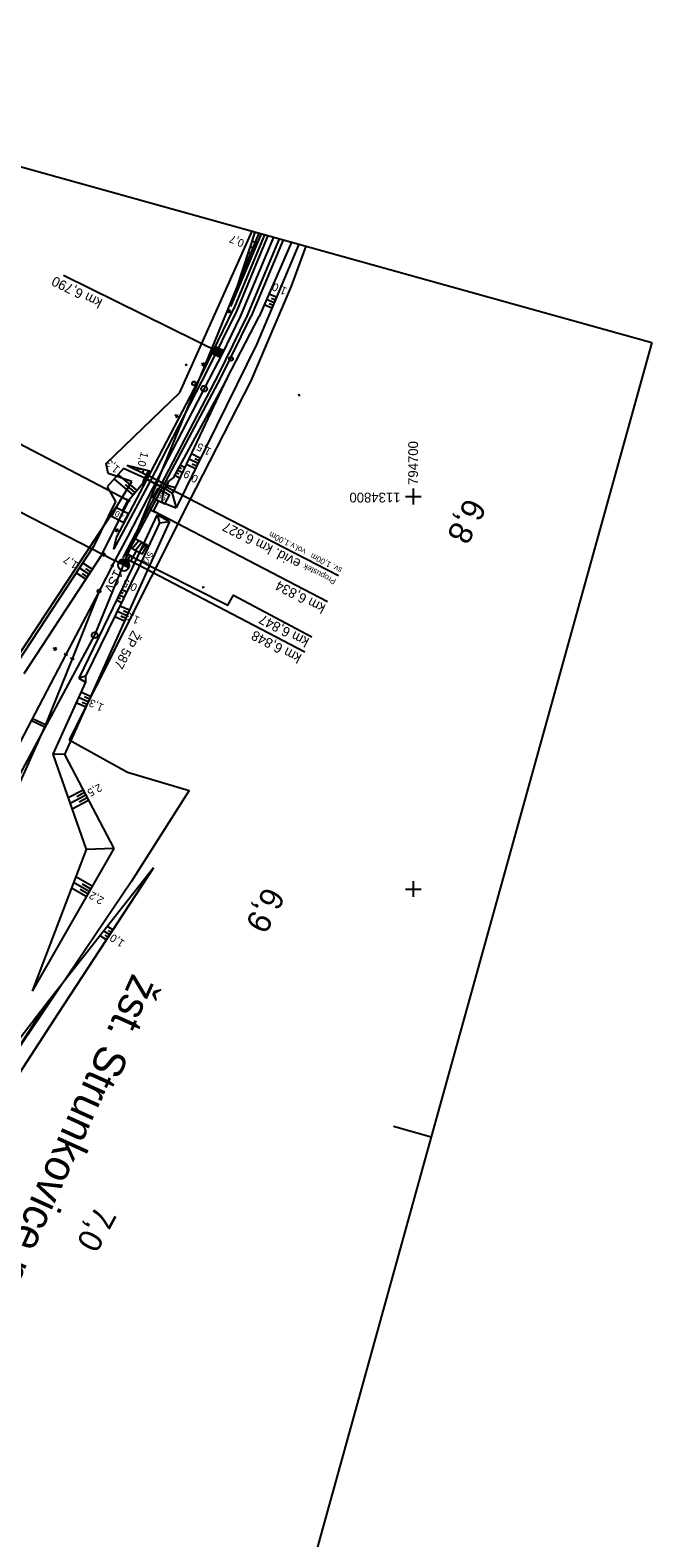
# Model space of a CAD drawing. Extents: x -795094 to -794639, y -1135368 to -1134681.
# Drawn here: x -794797.7 to -794639.2, y -1135065.2 to -1134681.2 of the extents above; entities that cross this region are included whole.
import ezdxf

# ---------------------------------------------------------------- set-up
doc = ezdxf.new("R2010")
doc.units = 0
for name, color, linetype in [('0381KM005-009P - Vrstva 1', 7, 'Continuous'), ('0381KM005-009P - Vrstva 19', 7, 'Continuous'), ('0381KM005-009P - Vrstva 2', 7, 'Continuous'), ('0381KM005-009P - Vrstva 23', 7, 'Continuous'), ('0381KM005-009P - Vrstva 28', 7, 'Continuous'), ('0381KM005-009P - Vrstva 3', 7, 'Continuous'), ('0381KM005-009P - Vrstva 33', 7, 'Continuous'), ('0381KM005-009P - Vrstva 4', 7, 'Continuous'), ('0381KM005-009P - Vrstva 48', 7, 'Continuous'), ('0381KM005-009P - Vrstva 49', 7, 'Continuous'), ('0381KM005-009P - Vrstva 5', 7, 'Continuous'), ('0381KM005-009P - Vrstva 51', 7, 'Continuous'), ('0381KM005-009P - Vrstva 6', 7, 'Continuous'), ('0381KM005-009P - Vrstva 7', 7, 'Continuous'), ('formát', 7, 'Continuous'), ('hran DP - hran DP', 7, 'Continuous'), ('krizky_1000 - souradnice', 7, 'Continuous'), ('krizky_1000 - Vrstva 1', 7, 'Continuous'), ('vyt_sit - polygon', 7, 'Continuous'), ('vyt_sit - stávající', 7, 'Continuous')]:
    doc.layers.add(name, color=color, linetype=linetype)

msp = doc.modelspace()

# ---------------------------------------------------------------- linework, layer by layer
at = {"layer": '0381KM005-009P - Vrstva 1'}
for points in [[(-794735.66, -1134733.94), (-794744.1, -1134754.13), (-794748.76, -1134763.69), (-794750.73, -1134767.6), (-794757.62, -1134780.92)], [(-794757.62, -1134780.92), (-794772.8, -1134810.07), (-794776.07, -1134816.32)], [(-794776.07, -1134816.32), (-794776.43, -1134817.02), (-794780.11, -1134824.07), (-794788.58, -1134840.28)], [(-794776.07, -1134816.32), (-794776.43, -1134817.02), (-794780.11, -1134824.07), (-794786.96, -1134841.36)], [(-794788.58, -1134840.28), (-794803.19, -1134868.16), (-794810.38, -1134881.86), (-794818.66, -1134897.6), (-794826.62, -1134912.5), (-794834.33, -1134926.85), (-794861.92, -1134977.99)], [(-794786.96, -1134841.36), (-794793.84, -1134858.32), (-794800.91, -1134874.12), (-794807.73, -1134887.87), (-794826.52, -1134924.29), (-794833.34, -1134937.13), (-794839.37, -1134947.86), (-794840.75, -1134950.16), (-794846.08, -1134958.61), (-794850.88, -1134965.55), (-794860.1, -1134978.74)]]:
    msp.add_lwpolyline(points, dxfattribs=at)
at = {"layer": '0381KM005-009P - Vrstva 19'}
for p, q in [((-794767.26, -1134793.5), (-794768.87, -1134796.52)), ((-794768.87, -1134796.52), (-794768.27, -1134795.41)), ((-794768.27, -1134795.41), (-794767.82, -1134794.57)), ((-794768.27, -1134795.41), (-794768.27, -1134795.41)), ((-794763.3, -1134797.99), (-794768.27, -1134795.41)), ((-794768.27, -1134795.41), (-794763.33, -1134798.06)), ((-794767.82, -1134794.57), (-794767.26, -1134793.5)), ((-794767.82, -1134794.57), (-794767.82, -1134794.57)), ((-794762.85, -1134797.19), (-794767.82, -1134794.57)), ((-794762.89, -1134797.15), (-794767.82, -1134794.57)), ((-794763.85, -1134798.98), (-794762.37, -1134796.11)), ((-794762.89, -1134797.15), (-794763.33, -1134798.06)), ((-794762.85, -1134797.19), (-794762.89, -1134797.15)), ((-794762.37, -1134796.11), (-794762.85, -1134797.19)), ((-794763.3, -1134797.99), (-794763.85, -1134798.98)), ((-794763.33, -1134798.06), (-794763.3, -1134797.99)), ((-794719.1, -1134820.2), (-794763.06, -1134797.51))]:
    msp.add_line(p, q, dxfattribs=at)
at = {"layer": '0381KM005-009P - Vrstva 2'}
for p, q in [((-794815.95, -1134795.81), (-794776.07, -1134816.32)), ((-794775.14, -1134816.79), (-794776.07, -1134816.32)), ((-794774.93, -1134816.49), (-794774.77, -1134816.98)), ((-794774.61, -1134816.22), (-794774.29, -1134817.23)), ((-794774.26, -1134816.06), (-794773.81, -1134817.48)), ((-794773.89, -1134816), (-794773.33, -1134817.72)), ((-794773.47, -1134816.05), (-794772.86, -1134817.97)), ((-794773, -1134816.26), (-794772.46, -1134817.95)), ((-794772.54, -1134818.13), (-794775.14, -1134816.79)), ((-794772.54, -1134818.13), (-794772.54, -1134818.13)), ((-794780.11, -1134824.07), (-794786.96, -1134841.36)), ((-794788.14, -1134840.51), (-794789.03, -1134840.05)), ((-794786.49, -1134841.55), (-794787.42, -1134841.18))]:
    msp.add_line(p, q, dxfattribs=at)
for points in [[(-794776.07, -1134816.32), (-794776.43, -1134817.02), (-794780.11, -1134824.07), (-794788.58, -1134840.28)], [(-794776.64, -1134817.99), (-794776.43, -1134817.02), (-794777.1, -1134817.76)]]:
    msp.add_lwpolyline(points, dxfattribs=at)
msp.add_circle((-794780.11, -1134824.07), 0.4, dxfattribs=at)
for start, end in [(332.7997, 152.7606), (152.7102, 333.1797)]:
    msp.add_arc((-794773.84, -1134817.46), 1.46, start, end, dxfattribs=at)
at = {"layer": '0381KM005-009P - Vrstva 28'}
msp.add_line((-794746.44, -1134764.88), (-794746.48, -1134764.97), dxfattribs=at)
msp.add_circle((-794746.46, -1134764.93), 0.5, dxfattribs=at)
at = {"layer": '0381KM005-009P - Vrstva 3'}
for p, q in [((-794748.76, -1134763.69), (-794789.21, -1134743.71)), ((-794750.35, -1134762.39), (-794749.67, -1134764.36)), ((-794750.12, -1134761.92), (-794749.2, -1134764.59)), ((-794749.64, -1134762.15), (-794748.96, -1134764.11)), ((-794749.16, -1134762.38), (-794748.73, -1134763.64)), ((-794748.69, -1134762.61), (-794748.5, -1134763.16)), ((-794750.81, -1134763.35), (-794750.63, -1134763.89)), ((-794750.58, -1134762.87), (-794750.15, -1134764.12))]:
    msp.add_line(p, q, dxfattribs=at)
msp.add_lwpolyline([(-794748.32, -1134762.79), (-794749.2, -1134764.59), (-794750.99, -1134763.71), (-794750.12, -1134761.92)], close=True, dxfattribs=at)
at = {"layer": '0381KM005-009P - Vrstva 33'}
msp.add_line((-794768.83, -1134796.2), (-794767.55, -1134793.7), dxfattribs=at)
at = {"layer": '0381KM005-009P - Vrstva 4'}
for points in [[(-794737.95, -1134733.31), (-794745.79, -1134752.29)], [(-794737.06, -1134733.55), (-794744.97, -1134752.65)], [(-794734.21, -1134734.35), (-794742.45, -1134754.09)], [(-794733.14, -1134734.64), (-794741.33, -1134754.03)], [(-794744.97, -1134752.65), (-794752.57, -1134767.89), (-794767.17, -1134796.25), (-794776.32, -1134813.35), (-794775.69, -1134810.46), (-794767.89, -1134795.76), (-794753.75, -1134768.59), (-794745.79, -1134752.29)], [(-794742.45, -1134754.09), (-794749.67, -1134768.83), (-794764.43, -1134797.23), (-794773.98, -1134815.47), (-794772.27, -1134813.39), (-794763.8, -1134797.42), (-794749.03, -1134769.75), (-794741.33, -1134754.03)]]:
    msp.add_lwpolyline(points, dxfattribs=at)
at = {"layer": '0381KM005-009P - Vrstva 48'}
for p, q in [((-794739.8, -1134735.54), (-794741.14, -1134734.97)), ((-794740.97, -1134738.3), (-794742.08, -1134737.83)), ((-794740.39, -1134736.92), (-794741.61, -1134736.4)), ((-794740.68, -1134737.61), (-794741.26, -1134737.36)), ((-794740.09, -1134736.23), (-794740.73, -1134735.96)), ((-794736.03, -1134752.03), (-794738.01, -1134751.2)), ((-794735.45, -1134750.65), (-794737.41, -1134749.82)), ((-794734.87, -1134749.26), (-794736.81, -1134748.45)), ((-794735.74, -1134751.34), (-794736.72, -1134750.92)), ((-794735.16, -1134749.96), (-794736.13, -1134749.54)), ((-794754.22, -1134790.28), (-794756.53, -1134789.14)), ((-794770.26, -1134792.73), (-794770.4, -1134793.3)), ((-794769.53, -1134792.91), (-794769.62, -1134793.27)), ((-794768.8, -1134793.1), (-794769.03, -1134793.97)), ((-794760.11, -1134793.21), (-794758.79, -1134793.93)), ((-794759.75, -1134792.55), (-794759.11, -1134792.9)), ((-794759.39, -1134791.89), (-794758.15, -1134792.57)), ((-794755.55, -1134792.97), (-794757.81, -1134791.86)), ((-794754.88, -1134791.63), (-794757.17, -1134790.5)), ((-794755.21, -1134792.3), (-794756.35, -1134791.74)), ((-794754.55, -1134790.95), (-794755.7, -1134790.39)), ((-794771.4, -1134799.56), (-794776.25, -1134795.52)), ((-794770.44, -1134798.41), (-794775.25, -1134794.4)), ((-794770.92, -1134798.98), (-794773.33, -1134796.97)), ((-794760.82, -1134794.53), (-794759.43, -1134795.29)), ((-794760.46, -1134793.87), (-794759.79, -1134794.24)), ((-794783.51, -1134821.05), (-794785.98, -1134819.43)), ((-794782.69, -1134819.79), (-794785.16, -1134818.18)), ((-794783.1, -1134820.42), (-794784.34, -1134819.61)), ((-794781.87, -1134818.54), (-794784.33, -1134816.93)), ((-794782.28, -1134819.17), (-794783.51, -1134818.36)), ((-794774.33, -1134823.66), (-794773.01, -1134824.29)), ((-794775.63, -1134826.36), (-794774.33, -1134826.99)), ((-794775.3, -1134825.69), (-794774.65, -1134826)), ((-794774.98, -1134825.01), (-794773.67, -1134825.64)), ((-794772.39, -1134828.99), (-794774.79, -1134827.92)), ((-794774.65, -1134824.34), (-794774, -1134824.65)), ((-794773.62, -1134831.73), (-794776.11, -1134830.61)), ((-794773.01, -1134830.36), (-794775.45, -1134829.27)), ((-794773.32, -1134831.05), (-794774.55, -1134830.49)), ((-794772.7, -1134829.68), (-794773.91, -1134829.14)), ((-794782.26, -1134850.93), (-794784.73, -1134849.82)), ((-794782.56, -1134851.61), (-794783.8, -1134851.06)), ((-794783.49, -1134853.67), (-794785.97, -1134852.55)), ((-794782.87, -1134852.3), (-794785.35, -1134851.19)), ((-794783.18, -1134852.98), (-794784.42, -1134852.43)), ((-794784.18, -1134874.77), (-794788, -1134876.78)), ((-794783.48, -1134876.09), (-794787.5, -1134878.21)), ((-794782.78, -1134877.42), (-794787, -1134879.64)), ((-794783.83, -1134875.43), (-794785.79, -1134876.46)), ((-794783.13, -1134876.76), (-794785.19, -1134877.84)), ((-794781.89, -1134899.28), (-794786.07, -1134896.89)), ((-794783.38, -1134901.88), (-794787.15, -1134899.73)), ((-794782.63, -1134900.58), (-794786.61, -1134898.31)), ((-794783, -1134901.23), (-794784.94, -1134900.12)), ((-794782.26, -1134899.93), (-794784.3, -1134898.76)), ((-794778.21, -1134912.91), (-794779.82, -1134911.86)), ((-794777.39, -1134911.65), (-794778.88, -1134910.67)), ((-794777.8, -1134912.28), (-794778.58, -1134911.77)), ((-794776.57, -1134910.4), (-794777.95, -1134909.49)), ((-794776.98, -1134911.03), (-794777.7, -1134910.55))]:
    msp.add_line(p, q, dxfattribs=at)
at = {"layer": '0381KM005-009P - Vrstva 49'}
for p, q in [((-794740.37, -1134732.63), (-794746.6, -1134751.57)), ((-794738.76, -1134733.08), (-794746.6, -1134751.57)), ((-794729.18, -1134735.74), (-794739.85, -1134761.11)), ((-794731.07, -1134735.22), (-794739.3, -1134754.18)), ((-794747.45, -1134769.82), (-794739.3, -1134754.18)), ((-794739.85, -1134761.11), (-794760.44, -1134802.9)), ((-794757.66, -1134766.37), (-794758.14, -1134766.52)), ((-794757.97, -1134766.21), (-794757.82, -1134766.69)), ((-794747.45, -1134769.82), (-794761.22, -1134795.28)), ((-794760.61, -1134797.81), (-794747.45, -1134769.82)), ((-794728.89, -1134774.12), (-794729.36, -1134774.28)), ((-794729.21, -1134773.96), (-794729.05, -1134774.44)), ((-794773.87, -1134792.87), (-794778.08, -1134797.54)), ((-794768.27, -1134795.41), (-794773.87, -1134792.87)), ((-794773.02, -1134792.01), (-794767.82, -1134794.57)), ((-794773.02, -1134792.01), (-794767.26, -1134793.5)), ((-794772.33, -1134800.68), (-794768.87, -1134796.52)), ((-794768.27, -1134795.41), (-794768.87, -1134796.52)), ((-794767.82, -1134794.57), (-794767.26, -1134793.5)), ((-794762.37, -1134796.11), (-794763.85, -1134798.98)), ((-794762.85, -1134797.19), (-794762.37, -1134796.11)), ((-794760.61, -1134797.81), (-794762.85, -1134797.19)), ((-794761.22, -1134795.28), (-794762.37, -1134796.11)), ((-794779.34, -1134814.68), (-794772.33, -1134800.68)), ((-794778.08, -1134797.54), (-794775.92, -1134801.3)), ((-794763.85, -1134798.98), (-794764.14, -1134801.43)), ((-794763.3, -1134797.99), (-794763.85, -1134798.98)), ((-794763.3, -1134797.99), (-794761.44, -1134799.24)), ((-794761.44, -1134799.24), (-794760.61, -1134797.81)), ((-794761.44, -1134799.24), (-794760.44, -1134802.9)), ((-794775.92, -1134801.3), (-794781.56, -1134812.71)), ((-794765.33, -1134804.62), (-794771.57, -1134817.97)), ((-794765.33, -1134804.62), (-794764.66, -1134806.73)), ((-794765.33, -1134804.62), (-794762.15, -1134806.37)), ((-794764.14, -1134801.43), (-794760.44, -1134802.9)), ((-794764.66, -1134806.73), (-794770.02, -1134818.19)), ((-794762.15, -1134806.37), (-794768.04, -1134819.3)), ((-794764.66, -1134806.73), (-794762.15, -1134806.37)), ((-794781.56, -1134812.71), (-794806.26, -1134850.22)), ((-794779.34, -1134814.68), (-794799.26, -1134845.15)), ((-794768.04, -1134819.3), (-794788.91, -1134865.74)), ((-794771.57, -1134817.97), (-794785.26, -1134846.3)), ((-794770.02, -1134818.19), (-794783.54, -1134845.78)), ((-794753.32, -1134823.06), (-794753.8, -1134823.21)), ((-794753.64, -1134822.9), (-794753.49, -1134823.38)), ((-794783.54, -1134845.78), (-794785.26, -1134846.3)), ((-794785.26, -1134846.3), (-794783.58, -1134847.29)), ((-794783.54, -1134845.78), (-794783.58, -1134847.29)), ((-794783.58, -1134847.29), (-794791.9, -1134865.62)), ((-794791.9, -1134865.62), (-794783.41, -1134889.91)), ((-794788.91, -1134865.74), (-794791.9, -1134865.62)), ((-794788.91, -1134865.74), (-794776.38, -1134889.62)), ((-794776.38, -1134889.62), (-794797.15, -1134926.02)), ((-794783.41, -1134889.91), (-794797.15, -1134926.02)), ((-794776.38, -1134889.62), (-794783.41, -1134889.91)), ((-794766.19, -1134894.56), (-794792.99, -1134928.57)), ((-794766.19, -1134894.56), (-794790.5, -1134931.65)), ((-794790.5, -1134931.65), (-794824.29, -1134983.58)), ((-794792.99, -1134928.57), (-794819.56, -1134969.3)), ((-794792.99, -1134928.57), (-794819.08, -1134962.42))]:
    msp.add_line(p, q, dxfattribs=at)
at = {"layer": '0381KM005-009P - Vrstva 5'}
for p, q in [((-794808.79, -1134782.22), (-794772.81, -1134800.95)), ((-794772.14, -1134801.3), (-794773.47, -1134800.61)), ((-794766.9, -1134803.37), (-794765.57, -1134804.07)), ((-794721.88, -1134826.8), (-794766.23, -1134803.72))]:
    msp.add_line(p, q, dxfattribs=at)
for points in [[(-794772.81, -1134800.95), (-794774.19, -1134803.61), (-794775.74, -1134802.81), (-794776.9, -1134805.02), (-794773.79, -1134806.64), (-794772.64, -1134804.42), (-794774.19, -1134803.61)], [(-794766.23, -1134803.72), (-794764.85, -1134801.06), (-794763.3, -1134801.87), (-794762.14, -1134799.65), (-794765.25, -1134798.03), (-794766.4, -1134800.25), (-794764.85, -1134801.06)]]:
    msp.add_lwpolyline(points, dxfattribs=at)
at = {"layer": '0381KM005-009P - Vrstva 51'}
msp.add_lwpolyline([(-794871.74, -1135021.34), (-794845.86, -1135006.13), (-794837.37, -1134998.39), (-794824.29, -1134983.58), (-794790.5, -1134931.65), (-794766.19, -1134894.56)], dxfattribs=at)
at = {"layer": '0381KM005-009P - Vrstva 6'}
for p, q in [((-794773.1, -1134816.84), (-794772.18, -1134815.08)), ((-794771.74, -1134815.31), (-794772.62, -1134814.85))]:
    msp.add_line(p, q, dxfattribs=at)
msp.add_lwpolyline([(-794772.18, -1134815.08), (-794747.28, -1134827.67), (-794745.87, -1134825.09), (-794725.88, -1134835.7)], dxfattribs=at)
at = {"layer": '0381KM005-009P - Vrstva 7'}
for p, q in [((-794747.36, -1134752.67), (-794746.44, -1134753.06)), ((-794747.09, -1134753.33), (-794746.71, -1134752.4)), ((-794753.12, -1134766.56), (-794754.01, -1134766.1)), ((-794753.33, -1134765.88), (-794753.79, -1134766.77)), ((-794755.87, -1134771.14), (-794755.92, -1134771.23)), ((-794759.86, -1134779.78), (-794760.75, -1134779.32)), ((-794760.07, -1134779.1), (-794760.53, -1134779.99)), ((-794775.17, -1134808.86), (-794776.06, -1134808.4)), ((-794775.38, -1134808.18), (-794775.84, -1134809.07)), ((-794771.69, -1134813.25), (-794770.09, -1134811.26)), ((-794769.2, -1134811.73), (-794770.8, -1134813.71)), ((-794769.92, -1134814.17), (-794768.32, -1134812.19)), ((-794778.43, -1134815.06), (-794779.32, -1134814.6)), ((-794778.65, -1134814.39), (-794779.11, -1134815.27)), ((-794772.64, -1134816.14), (-794771.31, -1134816.83)), ((-794727.67, -1134839.67), (-794771.97, -1134816.49)), ((-794790.89, -1134839.08), (-794791.78, -1134838.62)), ((-794791.11, -1134838.41), (-794791.57, -1134839.3)), ((-794797.37, -1134857.06), (-794793.96, -1134858.64)), ((-794797.09, -1134856.53), (-794793.74, -1134858.08))]:
    msp.add_line(p, q, dxfattribs=at)
msp.add_lwpolyline([(-794771.97, -1134816.49), (-794770.58, -1134813.83), (-794769.03, -1134814.64), (-794767.87, -1134812.42), (-794770.97, -1134810.8), (-794772.13, -1134813.02), (-794770.58, -1134813.83)], dxfattribs=at)
for centre, radius in [((-794755.9, -1134771.19), 0.5), ((-794753.29, -1134772.54), 0.75)]:
    msp.add_circle(centre, radius, dxfattribs=at)
at = {"layer": 'formát'}
for p, q in [((-794925.31, -1134681.22), (-794639.16, -1134760.77)), ((-794639.16, -1134760.77), (-794695.41, -1134963.1)), ((-794705.05, -1134960.42), (-794695.41, -1134963.1)), ((-794705.05, -1134960.42), (-794695.41, -1134963.1)), ((-794695.41, -1134963.1), (-794751.67, -1135165.42))]:
    msp.add_line(p, q, dxfattribs=at)
at = {"layer": 'hran DP - hran DP'}
for p, q in [((-794759.53, -1134773.54), (-794741.05, -1134732.44)), ((-794727.43, -1134736.23), (-794731.15, -1134746.39)), ((-794731.15, -1134746.39), (-794741.45, -1134770.5)), ((-794778.33, -1134791.56), (-794759.53, -1134773.54)), ((-794741.45, -1134770.5), (-794758.9, -1134804.63)), ((-794777.82, -1134794.18), (-794778.33, -1134791.56)), ((-794771.78, -1134796.16), (-794777.82, -1134794.18)), ((-794775.44, -1134802.2), (-794771.78, -1134796.16)), ((-794808.02, -1134851.51), (-794775.44, -1134802.2)), ((-794758.9, -1134804.63), (-794759.9, -1134806.76)), ((-794759.9, -1134806.76), (-794787.72, -1134861.99)), ((-794787.72, -1134861.99), (-794772.84, -1134870.22)), ((-794772.84, -1134870.22), (-794757.13, -1134874.85)), ((-794757.13, -1134874.85), (-794771.93, -1134898.11)), ((-794771.93, -1134898.11), (-794808.62, -1134952.39))]:
    msp.add_line(p, q, dxfattribs=at)
at = {"layer": 'krizky_1000 - Vrstva 1'}
for points in [[(-794702, -1134800), (-794698, -1134800)], [(-794700, -1134798), (-794700, -1134802)], [(-794702, -1134900), (-794698, -1134900)], [(-794700, -1134898), (-794700, -1134902)]]:
    msp.add_lwpolyline(points, dxfattribs=at)
at = {"layer": 'vyt_sit - polygon'}
for p, q in [((-794781.23, -1134835.33), (-794739.33, -1134732.92)), ((-794869.14, -1134998.77), (-794781.23, -1134835.33))]:
    msp.add_line(p, q, dxfattribs=at)
at = {"layer": 'vyt_sit - stávající'}
msp.add_line((-794781.21, -1134835.29), (-794781.25, -1134835.37), dxfattribs=at)
msp.add_circle((-794781.23, -1134835.33), 0.756, dxfattribs=at)

# ---------------------------------------------------------------- texts
at = {"layer": '0381KM005-009P - Vrstva 19'}
for s, height, p in [('evid. km 6,827', 2.5, (-794728.46, -1134816.29)), ('sv. 1,00m   vol.v.1,00m', 1.5, (-794717.99, -1134818.3)), ('Propustek', 1.5, (-794719.55, -1134821.16))]:
    msp.add_text(s, height=height, rotation=152.7057, dxfattribs=at).set_placement(p)
at = {"layer": '0381KM005-009P - Vrstva 2'}
msp.add_text('1Sv', height=2.5, rotation=242.4084, dxfattribs=at).set_placement((-794776.11, -1134818.38))
at = {"layer": '0381KM005-009P - Vrstva 23'}
msp.add_text('žst. Strunkovice nad Volyňkou', height=8, rotation=245.663, dxfattribs=at).set_placement((-794771.54, -1134921.22))
at = {"layer": '0381KM005-009P - Vrstva 3'}
msp.add_text('km 6,790', height=2.5, rotation=153.7108, dxfattribs=at).set_placement((-794779.06, -1134749.9))
at = {"layer": '0381KM005-009P - Vrstva 48'}
for s, rotation, p in [('0,7', 157.0225, (-794742.9, -1134734.77)), ('1,0', 157.1828, (-794732.04, -1134746.95)), ('1,0', 255.4428, (-794769.39, -1134788.47)), ('1,5', 153.7759, (-794751.28, -1134787.9)), ('1,3', 140.2012, (-794774.66, -1134792.71)), ('0,9', 151.5692, (-794754.62, -1134794.92)), ('1,7', 146.832, (-794785.24, -1134816.96)), ('0,5', 154.2119, (-794770.15, -1134822.51)), ('1,3', 155.7895, (-794769.58, -1134830.83)), ('1,3', 155.7895, (-794778.72, -1134853.04)), ('2,5', 207.6821, (-794780.03, -1134873.07)), ('2,2', 150.2833, (-794778.67, -1134902.33)), ('1,0', 146.755, (-794773.41, -1134913.32))]:
    msp.add_text(s, height=2, rotation=rotation, dxfattribs=at).set_placement(p)
at = {"layer": '0381KM005-009P - Vrstva 5'}
for s, height, rotation, p in [('55', 1.5, 332.5023, (-794765.41, -1134800.15)), ('40', 1.5, 152.5023, (-794773.63, -1134804.52)), ('km 6,834', 2.5, 152.5023, (-794722.13, -1134827.68))]:
    msp.add_text(s, height=height, rotation=rotation, dxfattribs=at).set_placement(p)
at = {"layer": '0381KM005-009P - Vrstva 6'}
for s, height, rotation, p in [('  A ', 1, 242.3746, (-794773.07, -1134814.62)), ('Sv1', 1.5, 242.5023, (-794767.44, -1134813.81)), ('km 6,847', 2.5, 152.3746, (-794726.31, -1134836.27))]:
    msp.add_text(s, height=height, rotation=rotation, dxfattribs=at).set_placement(p)
at = {"layer": '0381KM005-009P - Vrstva 7'}
for s, height, rotation, p in [('6,8', 6, 242.6352, (-794686.43, -1134800.02)), ('km 6,848', 2.5, 152.3746, (-794728.26, -1134840.39)), ('6,9', 6, 242.3222, (-794737.76, -1134899.06)), ('7,0', 6, 241.6619, (-794780.73, -1134980.29))]:
    msp.add_text(s, height=height, rotation=rotation, dxfattribs=at).set_placement(p)
at = {"layer": 'krizky_1000 - souradnice'}
for s, rotation, p in [('794700', 90, (-794698.79, -1134797.05)), ('1134800', 180, (-794703.26, -1134799.02))]:
    msp.add_text(s, height=2.5, rotation=rotation, dxfattribs=at).set_placement(p)
at = {"layer": 'vyt_sit - stávající'}
msp.add_text('ŽP 587', height=2.4, rotation=242.405, dxfattribs=at).set_placement((-794771.57, -1134833.95))

doc.saveas('drawing.dxf')
